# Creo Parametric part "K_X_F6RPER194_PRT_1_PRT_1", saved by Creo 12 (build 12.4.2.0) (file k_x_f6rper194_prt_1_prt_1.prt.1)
Units: Custom; MM, KILOGRAM, SECS

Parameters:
  PTC_WM_ITERATION = "0"
  PTC_WM_VERSION = "-.0"
  PTC_WM_LIFECYCLE_STATE = "In Work"
  PTC_WM_LIFECYCLE = "MO_CADDocument"
  PTC_WM_CREATED_BY = "Maximilian Roepper (Z0017RMS: MO)"
  PTC_WM_CREATED_ON = "18-Sep-26 11:36:42 AM"
  PTC_WM_MODIFIED_BY = "Maximilian Roepper (Z0017RMS: MO)"
  PTC_WM_MODIFIED_ON = "18-Sep-26 11:36:46 AM"
  PDMLINKNUMBER = "PDM000071455311"
  PTC_WM_NAME = "k_x_f6rper194_prt_1_prt_1.prt"
  PTC_WM_NUMBER = "PDM000071455311"

Other parameters: WEIGHT, WEIGHT_FACTOR, WEIGHT_ADD, _MASS_TEMP, _DIFF_TEMP, MC_ERRORS, SUPPLIER

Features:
  1. coordinate system
  2. datum plane "PRT_YZ"
  3. datum plane "PRT_XY"
  4. datum plane "PRT_XZ"
  5. coordinate system
  6. datum axis
  7. datum axis
  8. datum axis
  9. coordinate system
  10. imported feature
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
Other named items: PRT, SIEMENS_MO, DRW_VIEW_ORG, PRT_X, PRT_Y, PRT_Z, CS0, ROUGH_GROB

Layers: 00_STD_CSYS-KSYS, 01_STD_PLANES-EBENEN, 02_STD_AXES-ACHSEN, 03_STD_CSYS-KSYS, 24_IMPORT_FEAT-IMPORT_KE

Surfaces: 14 plane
